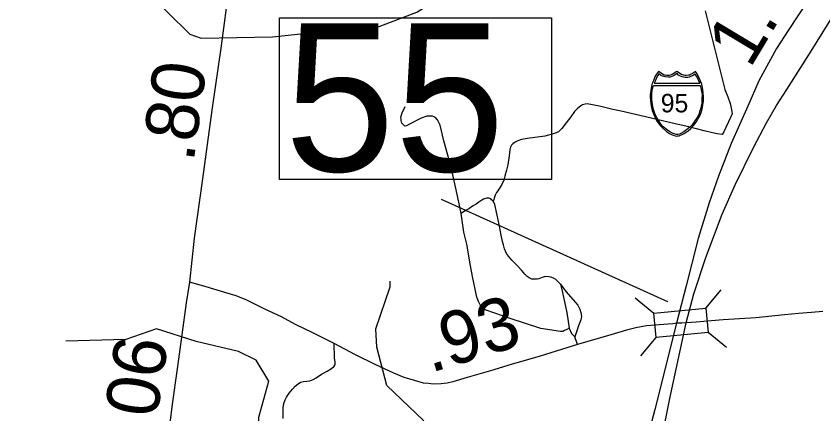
# Model space of a CAD drawing. Extents: x 2290615 to 2522933, y 819489 to 1012715.
# Drawn here: x 2353015 to 2360649, y 877207 to 880969 of the extents above; entities that cross this region are included whole.
import ezdxf

# ---------------------------------------------------------------- set-up
doc = ezdxf.new("R2010")
doc.units = 0
for name, color, linetype in [('Exist Hydrographic Misc Water Feature', 7, 'Continuous'), ('Exist Road Non-System Type 51', 7, 'Continuous'), ('Exist Road Primary Interstate Divided Center Attributed', 7, 'Continuous'), ('Exist Road Primary Interstate Mileage Hundredths English Label', 7, 'Continuous'), ('Exist Road Primary Interstate Shield CELL', 7, 'Continuous'), ('Exist Road Primary Interstate Shield Number Label', 7, 'Continuous'), ('Exist Road Secondary Mileage Hundredths English Label', 7, 'Continuous'), ('Exist Road Secondary Structure Standard Bridge CELL', 7, 'Continuous'), ('Exist Road Secondary Structure Standard Bridge Number Label', 7, 'Continuous'), ('Exist Road Secondary Type 51 Attributed', 7, 'Continuous')]:
    doc.layers.add(name, color=color, linetype=linetype)

msp = doc.modelspace()

# ---------------------------------------------------------------- linework, layer by layer
at = {"layer": 'Exist Hydrographic Misc Water Feature'}
for points in [[(2352876.3, 881453.7), (2353253.2, 881357.5), (2353760.3, 881378.3), (2353961.2, 881350.5), (2354237.2, 881217.4), (2354659.2, 880798), (2354767.3, 880759.8), (2355442.3, 880774.4), (2355825.3, 880813), (2356358.3, 880834.9), (2356806.3, 881007.4), (2356954.4, 881102.1), (2357328.4, 881248.8), (2357534.2, 881381.9), (2357699.3, 881542.9), (2357931.2, 881670.6), (2358210.3, 881984.1), (2358433.4, 882134.4), (2358724.4, 882238.1), (2359031.3, 882277), (2359388.3, 882363.8), (2359788.4, 882409.8), (2360095.3, 882520.9), (2360517.3, 882728.5)], [(2360836.4, 876298.2), (2360519.4, 876288.5), (2360344.3, 876343.7), (2359570.4, 876935.7), (2359378.3, 877016.4), (2359128.3, 876970), (2358920.4, 876941.8), (2358412.3, 876921), (2358064.3, 876798.4), (2357382.3, 876698.3), (2357173.4, 876739), (2357005.2, 876860.1), (2356869.3, 877143.4), (2356523.3, 877473.8), (2356427.4, 877837.6), (2356417.3, 878011.1), (2356554.3, 878407.3), (2356553.3, 878463.1)], [(2356375.3, 873948.3), (2356380.2, 874156.1), (2356412.2, 874196.8), (2356403.4, 874262.1), (2356192.4, 874529.1), (2355919.3, 875000.5), (2355624.2, 875369.2), (2355581.3, 875469.2), (2355446.2, 876267.8), (2355316.2, 876699.1), (2355310.2, 877174.8), (2355406.2, 877516.7), (2355287.3, 877715.4), (2355120.2, 877797.1), (2354718.3, 877892.3), (2354342.2, 878011.5), (2354052.3, 877910.9), (2353486.3, 877894.3)]]:
    msp.add_lwpolyline(points, dxfattribs=at)
at = {"layer": 'Exist Road Non-System Type 51'}
msp.add_line((2358325.3, 877861.3), (2358301.2, 877935.5), dxfattribs=at)
msp.add_line((2358325.3, 877861.3), (2358301.2, 877935.5), dxfattribs=at)
for points in [[(2359536.4, 881019.3), (2359720.3, 880274.4), (2359749, 880204.5), (2359772.5, 880144.1), (2359779.2, 880112.8), (2359788.1, 880068), (2359789.2, 880044.5), (2359774.7, 880008.7), (2359755.7, 879968.4), (2359731.1, 879916.9), (2359712.1, 879875.5), (2359696.4, 879849.8), (2359647, 879856.3), (2359603.3, 879865.5), (2359525.1, 879885), (2359379, 879921.9), (2359252.5, 879949.5), (2358971.8, 880016.3), (2358740.6, 880070.3), (2358662.4, 880085.3), (2358546.6, 880112.9), (2358467.6, 880131.3), (2358417, 880138.3), (2358400.1, 880137.5), (2358374, 880129), (2358356.6, 880118.9), (2358327.3, 880095.3), (2358299.6, 880067.7), (2358263.6, 880016.3), (2358219.1, 879958.7), (2358180, 879907.3), (2358145.7, 879874.6), (2358109.9, 879860.1), (2358016.3, 879835.1), (2357854.6, 879811), (2357795.8, 879800.6), (2357761.3, 879788.4), (2357737.5, 879777.6), (2357715.3, 879761.5), (2357703, 879748.5), (2357693, 879730.8), (2357686.1, 879704.7), (2357680, 879648.7), (2357667, 879563.5), (2357656.2, 879512.9), (2357640.1, 879454.6), (2357629.4, 879418.5), (2357609.5, 879377.1), (2357594.1, 879351), (2357581.1, 879331.8), (2357572.6, 879318), (2357560.4, 879300.4), (2357546.6, 879274.3), (2357537.4, 879246.6), (2357534.3, 879234.4), (2357528.6, 879218.1)], [(2357225, 879100.7), (2357195.1, 879254.1), (2357131.9, 879540.5), (2357063.1, 879789.6), (2357027.2, 879939), (2357012.9, 879968.8), (2357002.7, 879988.8), (2356982.4, 880010.6), (2356956.3, 880022.1), (2356926.2, 880023.9), (2356900.2, 880023.4), (2356848.6, 880004.9), (2356822.7, 879992.6), (2356763, 879960), (2356737.3, 879947.5), (2356709.3, 879931.2), (2356695.4, 879929.2), (2356689.3, 879931), (2356677.2, 879942.9), (2356665.1, 879956.8), (2356656.9, 879980.7), (2356656.7, 879994.7), (2356656.4, 880012.6), (2356667.9, 880052.7), (2356695.3, 880113.1)], [(2357225, 879100.7), (2357195.1, 879254.1), (2357131.9, 879540.5), (2357063.1, 879789.6), (2357027.2, 879939), (2357012.9, 879968.8), (2357002.7, 879988.8), (2356982.4, 880010.6), (2356956.3, 880022.1), (2356926.2, 880023.9), (2356900.2, 880023.4), (2356848.6, 880004.9), (2356822.7, 879992.6), (2356763, 879960), (2356737.3, 879947.5), (2356709.3, 879931.2), (2356695.4, 879929.2), (2356689.3, 879931), (2356677.2, 879942.9), (2356665.1, 879956.8), (2356656.9, 879980.7), (2356656.7, 879994.7), (2356656.4, 880012.6), (2356667.9, 880052.7), (2356695.3, 880113.1)], [(2357528.6, 879218.1), (2357514.4, 879232.8), (2357505.9, 879241.3), (2357496.7, 879245.1), (2357489.1, 879247.4), (2357479.1, 879247.4), (2357467.6, 879245.9), (2357455.3, 879245.1), (2357438.4, 879238.2), (2357423.1, 879229), (2357394.7, 879210.6), (2357366.4, 879189.9), (2357333.4, 879169.9), (2357299.6, 879147.7), (2357259, 879123.1), (2357225, 879100.7)], [(2358166.6, 878434.5), (2358145.2, 878456.1), (2358121.4, 878476.9), (2358098.4, 878489.1), (2358075.4, 878498.3), (2358057, 878503.7), (2358027.1, 878505.2), (2358010.2, 878502.9), (2357991.8, 878497.6), (2357975.7, 878491.4), (2357961.2, 878485.3), (2357944.3, 878481.5), (2357928.2, 878479.9), (2357910.5, 878481.5), (2357895.2, 878481.5), (2357882.2, 878486.1), (2357869.1, 878494.5), (2357851.5, 878506.8), (2357828.5, 878529), (2357795.5, 878565.1), (2357751.8, 878611.9), (2357706.6, 878660.2), (2357673.6, 878697.8), (2357655.9, 878723.9), (2357644.4, 878746.2), (2357636.8, 878768.4), (2357625.3, 878805.3), (2357616.8, 878838.3), (2357603.8, 878898.1), (2357584.6, 878997.1), (2357567, 879086.1), (2357544, 879186.6), (2357535.5, 879208.9), (2357528.6, 879218.1)], [(2358249.4, 878018.4), (2358225.3, 878005.7), (2358202.2, 877994.2), (2358187.3, 877986.2), (2358166.6, 877985), (2357980, 878015.1), (2357689, 878109.7), (2357544.5, 878159.8), (2357454.2, 878190.7), (2357438, 878200.6), (2357425.9, 878212.3), (2357405.6, 878238.1), (2357389.1, 878269.8), (2357374.7, 878309.7), (2357332.5, 878505.2), (2357306.8, 878642.8), (2357289.3, 878758.6), (2357278.7, 878810.4), (2357251.4, 878926.1), (2357225, 879100.7)], [(2358166.6, 878434.5), (2358185, 878353.3), (2358203.4, 878267), (2358217.2, 878207.2), (2358225.3, 878166.9), (2358249.4, 878018.4)], [(2358166.6, 878434.5), (2358216.6, 878365.4), (2358285.6, 878286), (2358330.5, 878234.2), (2358349.5, 878197.9), (2358359.8, 878165.1), (2358363.3, 878128.9), (2358359.8, 878096.1), (2358337.4, 878039.1), (2358301.2, 877935.5)], [(2358249.4, 878018.4), (2358269, 877967.8), (2358301.2, 877935.5)], [(2355543.1, 877163.4), (2355541.3, 877216.9), (2355541.3, 877263.5), (2355548.2, 877305), (2355560.3, 877339.5), (2355574.1, 877365.4), (2355600, 877403.4), (2355629.3, 877439.6), (2355655.2, 877467.2), (2355682.8, 877491.4), (2355707, 877506.9), (2355732.9, 877512.1), (2355765.6, 877517.3), (2355795, 877519), (2355826, 877531.1), (2355855.4, 877548.4), (2355903.7, 877581.2), (2355957.2, 877610.5), (2355998.6, 877634.7), (2356022.7, 877657.1), (2356033.1, 877674.4), (2356034.8, 877700.3), (2356027.9, 877734.8), (2356022.7, 877871.2)]]:
    msp.add_lwpolyline(points, dxfattribs=at)
at = {"layer": 'Exist Road Primary Interstate Divided Center Attributed'}
for points in [[(2359354.4, 878069.2), (2359426.5, 878342.4), (2359541.4, 878687.3), (2359694.9, 879094.6), (2359818, 879372.2), (2359993.6, 879725.3), (2360114.3, 879958.5), (2360209.7, 880124.3), (2360308.8, 880275.4), (2360538.6, 880638.4), (2360780.8, 881027.6), (2361055.3, 881466.9), (2361346.1, 881924.9), (2361925.2, 882862.8), (2362383.1, 883592.3), (2363024.8, 884596.3), (2363306.3, 885039.7), (2363437.3, 885262.5)], [(2363177.9, 885034.3), (2362912.6, 884627.1), (2362276.5, 883691.6), (2361726.5, 882891.9), (2361142.5, 882043.7), (2360796.1, 881546.8), (2360510.1, 881120.3), (2360318.7, 880834.3), (2360210.9, 880662.3), (2360043.7, 880356.9), (2359939.5, 880117.8), (2359781.9, 879764.7), (2359660.4, 879454.3), (2359573.4, 879201.4), (2359469.1, 878866.3), (2359354.2, 878416.4), (2359265.1, 878063.5)], [(2359265.1, 878063.5), (2359058.8, 877249.5), (2358758.3, 876114), (2358440.3, 874817.3), (2358283.1, 874241), (2358234.3, 874042.1), (2358057.4, 873344)], [(2358341.7, 873124.9), (2358369.7, 873265.3), (2358437.8, 873557.6), (2358464.7, 873708.3), (2358531.4, 874024.1), (2358666.8, 874705.6), (2358890.1, 875805.9), (2359199.1, 877353), (2359354.4, 878069.2)]]:
    msp.add_lwpolyline(points, dxfattribs=at)
at = {"layer": 'Exist Road Primary Interstate Shield CELL'}
for points in [[(2359267.7, 879834.9), (2359277.2, 879835.8), (2359289.9, 879838.2), (2359302.3, 879842.3), (2359316.4, 879848.5), (2359337.3, 879860.1), (2359354, 879869.9), (2359373.4, 879882.9), (2359399.5, 879906.6), (2359425.5, 879934), (2359448.5, 879965.1), (2359466.8, 879994.1), (2359482.8, 880027.2), (2359496.3, 880058.1), (2359506.9, 880093.5), (2359514, 880127.7), (2359517.6, 880163.4), (2359519.9, 880203), (2359517.3, 880247.5), (2359509.5, 880293.1), (2359502.2, 880321.4), (2359491.2, 880355.4), (2359482.2, 880377.1), (2359461.4, 880415.5), (2359442.6, 880445.1), (2359415.4, 880425.9), (2359397.6, 880416.5), (2359386.8, 880411.6), (2359375.6, 880409.4), (2359355.1, 880406.9), (2359342.3, 880407.5), (2359330.3, 880410.2), (2359320.2, 880412.4), (2359311.9, 880416.5), (2359267.7, 880445.1), (2359223.4, 880416.5), (2359214.2, 880412.2), (2359204.7, 880410.2), (2359195.5, 880407.7), (2359180.4, 880406.9), (2359168.8, 880407.3), (2359156.9, 880409.4), (2359147.5, 880411.4), (2359137, 880416.5), (2359091.9, 880445.1), (2359074.2, 880419.4), (2359059.7, 880394), (2359044.4, 880358), (2359034.8, 880330.2), (2359028, 880307.3), (2359019.7, 880265.4), (2359015.4, 880228.8), (2359014.6, 880203), (2359019.3, 880138.5), (2359026.4, 880104.1), (2359033.6, 880076.3), (2359057.5, 880016.3), (2359075.4, 879982.7), (2359090.8, 879958.5), (2359112.4, 879931.3), (2359124.1, 879918.4), (2359168.9, 879879.2), (2359198.8, 879858.8), (2359222.7, 879845.9), (2359234, 879841.6), (2359251.5, 879836.7)], [(2359097.3, 880424.3), (2359086.3, 880407.4), (2359073.6, 880384.6), (2359063.5, 880360.9), (2359053.1, 880334.7), (2359484.7, 880334.6), (2359474.6, 880357), (2359463.9, 880379.5), (2359452.6, 880400.1), (2359438.9, 880420), (2359414.7, 880404.8), (2359397.1, 880396.4), (2359382.9, 880391.5), (2359370.9, 880388.8), (2359352.3, 880387.4), (2359344, 880387.9), (2359318.1, 880393.7), (2359300.5, 880400.9), (2359283.8, 880412.1), (2359270.3, 880424.8), (2359236.1, 880404.1), (2359220.9, 880397.4), (2359203.5, 880393), (2359184.4, 880390.6), (2359155, 880393.7), (2359131.9, 880401.7), (2359112, 880412.1)], [(2359487.2, 880313.3), (2359491.9, 880301.1), (2359498.2, 880274.1), (2359501.5, 880253.2), (2359505, 880229.2), (2359503.8, 880188.1), (2359501.8, 880145.5), (2359497.9, 880120.3), (2359492.6, 880097.4), (2359485.5, 880071.9), (2359474, 880038.1), (2359458.1, 880009.4), (2359438.2, 879977.6), (2359416.7, 879949.7), (2359407.4, 879938.2), (2359389.7, 879919.5), (2359357.4, 879893.6), (2359333.9, 879876), (2359305.7, 879859.4), (2359291.4, 879853), (2359274.8, 879849.6), (2359261.1, 879850.5), (2359244.4, 879854.9), (2359231, 879858.6), (2359201.6, 879874.5), (2359177.7, 879890.5), (2359137.9, 879923.1), (2359116.5, 879948.2), (2359096.4, 879977.6), (2359078.6, 880007.7), (2359059.5, 880047.3), (2359046, 880087.3), (2359036.2, 880130.3), (2359029.6, 880183), (2359028.9, 880215), (2359030.9, 880245.9), (2359033.8, 880262), (2359037.7, 880282.1), (2359045.6, 880313.1)]]:
    msp.add_lwpolyline(points, close=True, dxfattribs=at)
at = {"layer": 'Exist Road Secondary Structure Standard Bridge CELL'}
for p, q in [((2359541.7, 878206.2), (2359685.7, 878380.9)), ((2358873.4, 878303.7), (2359048.1, 878159.8)), ((2359563.4, 877980.9), (2359738.1, 877837)), ((2358926.3, 877754.6), (2359070.3, 877929.3))]:
    msp.add_line(p, q, dxfattribs=at)
msp.add_lwpolyline([(2359048.1, 878159.8), (2359541.6, 878207.3), (2359563.8, 877976.8), (2359070.3, 877929.3)], close=True, dxfattribs=at)
at = {"layer": 'Exist Road Secondary Structure Standard Bridge Number Label'}
msp.add_line((2359181.7, 878268), (2357039.4, 879234.7), dxfattribs=at)
msp.add_lwpolyline([(2355505.5, 880951.5), (2358082.1, 880951.5), (2358082.1, 879422.3), (2355505.5, 879422.3)], close=True, dxfattribs=at)
at = {"layer": 'Exist Road Secondary Type 51 Attributed'}
for points in [[(2355216.9, 882626.6), (2355183.3, 882393.6), (2355108.2, 881790.2), (2355028, 881241.2), (2354955.5, 880689.6), (2354867.5, 880078.4), (2354779.5, 879428.4), (2354699.3, 878869.1), (2354654.4, 878451.7)], [(2354654.4, 878451.7), (2354625.1, 878256.2), (2354582, 877955.8), (2354538.8, 877633), (2354490.5, 877298), (2354457.7, 877018.4)], [(2359265.1, 878063.5), (2359228.8, 878059.6), (2359099.4, 878048.6), (2358981.1, 878040.1), (2358877.8, 878021.9), (2358790, 877996.9), (2358640.7, 877953), (2358325.3, 877861.3), (2357973.2, 877753.1), (2357700.3, 877673.9), (2357503.1, 877613.4), (2357283.9, 877550.8), (2357148.4, 877509.2), (2357094.6, 877498.6), (2357036.6, 877491.8), (2356960.7, 877488.9), (2356916.7, 877492.5), (2356870.6, 877495.8), (2356784.3, 877520.9), (2356688, 877551.8), (2356587.6, 877590.5), (2356411, 877672.7), (2356226.3, 877765.9), (2356022.7, 877871.2), (2355820.9, 877973.1), (2355656.9, 878052.5), (2355525.8, 878123.3), (2355367.1, 878197.5), (2355198, 878282.1), (2355097.9, 878321.8), (2354989.2, 878356.3), (2354811.5, 878408.1), (2354654.4, 878451.7)], [(2360649.3, 878175.1), (2360539.5, 878165.2), (2360418.9, 878154.7), (2360285.3, 878142.1), (2360014.9, 878115.9), (2359704.5, 878095.8), (2359450.7, 878074.8), (2359400.9, 878071.6), (2359354.4, 878069.2)], [(2359354.4, 878069.2), (2359315, 878066.1), (2359265.1, 878063.5)]]:
    msp.add_lwpolyline(points, dxfattribs=at)

# ---------------------------------------------------------------- texts
at = {"layer": 'Exist Road Primary Interstate Mileage Hundredths English Label'}
msp.add_text('1.73', height=500, rotation=59.04534, dxfattribs=at).set_placement((2359958.2, 880465.4))
at = {"layer": 'Exist Road Primary Interstate Shield Number Label'}
msp.add_text('95', height=175, dxfattribs=at).set_placement((2359114.8, 880058.6))
at = {"layer": 'Exist Road Secondary Mileage Hundredths English Label'}
for s, rotation, p in [('.80', 82.29001, (2354693.8, 879580.1)), ('.93', 17.05529, (2356934.4, 877592.8)), ('1.06', 81.5406, (2354263.9, 876607.2))]:
    msp.add_text(s, height=500, rotation=rotation, dxfattribs=at).set_placement(p)
at = {"layer": 'Exist Road Secondary Structure Standard Bridge Number Label'}
msp.add_text('55', height=1400, dxfattribs=at).set_placement((2355555.7, 879501.4))

doc.saveas('drawing.dxf')
